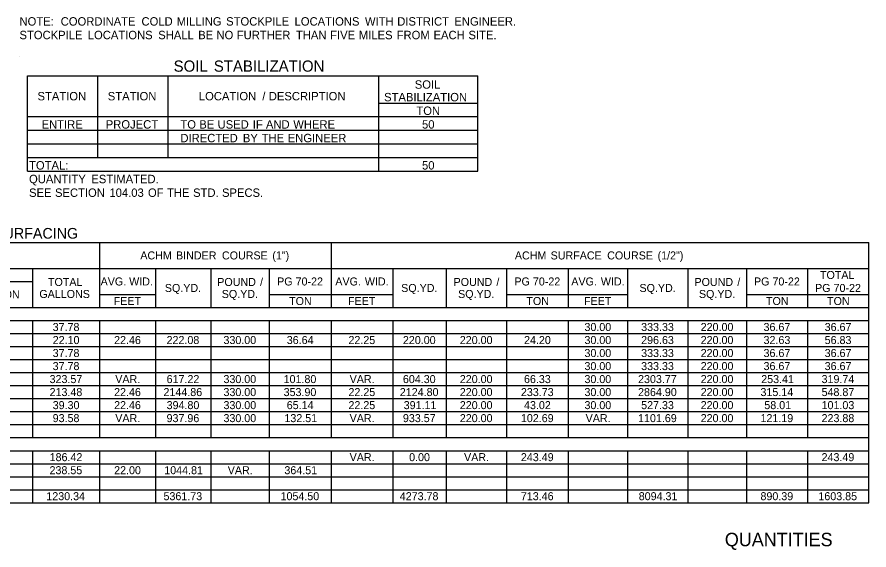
# Model space of a CAD drawing. Extents: x 1334738 to 1334853, y 402732 to 402753.
# Drawn here: x 1334837.83 to 1334853.05, y 402732.57 to 402742.09 of the extents above; entities that cross this region are included whole.
import ezdxf

# ---------------------------------------------------------------- set-up
doc = ezdxf.new("R2010")
doc.units = 0
doc.layers.add('Default', color=7, linetype='Continuous')
doc.layers.add('R_No Plot', color=7, linetype='Continuous')

msp = doc.modelspace()

# ---------------------------------------------------------------- linework, layer by layer
at = {"layer": 'Default'}
for p, q in [((1334837.87, 402741.381), (1334837.87, 402741.381)), ((1334838.016, 402741.04), (1334846.06, 402741.04)), ((1334838.016, 402739.334), (1334838.016, 402741.04)), ((1334838.016, 402739.334), (1334838.016, 402741.04)), ((1334839.272, 402739.577), (1334839.272, 402741.04)), ((1334840.527, 402739.577), (1334840.527, 402741.04)), ((1334844.293, 402739.334), (1334844.293, 402741.04)), ((1334846.06, 402739.334), (1334846.06, 402741.04)), ((1334846.06, 402739.334), (1334846.06, 402741.04)), ((1334844.293, 402740.552), (1334846.06, 402740.552)), ((1334838.016, 402740.309), (1334846.06, 402740.309)), ((1334838.016, 402740.309), (1334846.06, 402740.309)), ((1334839.272, 402739.577), (1334839.272, 402740.309)), ((1334840.527, 402739.577), (1334840.527, 402740.309)), ((1334844.293, 402739.577), (1334844.293, 402740.309)), ((1334838.016, 402740.065), (1334846.06, 402740.065)), ((1334838.016, 402739.821), (1334846.06, 402739.821)), ((1334838.016, 402739.577), (1334839.272, 402739.577)), ((1334838.016, 402739.577), (1334846.06, 402739.577)), ((1334838.016, 402739.334), (1334846.06, 402739.334)), ((1334821.913, 402738.063), (1334853.053, 402738.063)), ((1334839.307, 402736.901), (1334839.307, 402738.063)), ((1334843.444, 402737.598), (1334843.444, 402738.063)), ((1334843.444, 402736.901), (1334843.444, 402738.063)), ((1334853.053, 402733.647), (1334853.053, 402738.063)), ((1334853.053, 402733.415), (1334853.053, 402738.063)), ((1334828.745, 402737.598), (1334853.053, 402737.598)), ((1334838.11, 402736.901), (1334838.11, 402737.598)), ((1334838.11, 402736.901), (1334838.11, 402737.598)), ((1334840.306, 402736.901), (1334840.306, 402737.598)), ((1334841.294, 402736.901), (1334841.294, 402737.598)), ((1334842.34, 402736.901), (1334842.34, 402737.598)), ((1334844.547, 402737.598), (1334845.5, 402737.598)), ((1334844.547, 402736.901), (1334844.547, 402737.598)), ((1334845.5, 402736.901), (1334845.5, 402737.598)), ((1334846.581, 402736.901), (1334846.581, 402737.598)), ((1334847.685, 402736.901), (1334847.685, 402737.598)), ((1334848.742, 402737.598), (1334849.823, 402737.598)), ((1334848.742, 402736.901), (1334848.742, 402737.598)), ((1334849.823, 402736.901), (1334849.823, 402737.598)), ((1334850.868, 402736.901), (1334850.868, 402737.598)), ((1334851.961, 402736.901), (1334851.961, 402737.598)), ((1334830.929, 402737.366), (1334838.11, 402737.366)), ((1334839.307, 402737.133), (1334840.306, 402737.133)), ((1334840.306, 402736.901), (1334840.306, 402737.133)), ((1334842.34, 402737.133), (1334844.547, 402737.133)), ((1334843.444, 402736.901), (1334843.444, 402737.133)), ((1334844.547, 402736.901), (1334844.547, 402737.133)), ((1334846.581, 402737.133), (1334848.742, 402737.133)), ((1334847.685, 402736.901), (1334847.685, 402737.133)), ((1334848.742, 402736.901), (1334848.742, 402737.133)), ((1334850.868, 402737.133), (1334853.053, 402737.133)), ((1334821.913, 402736.901), (1334853.053, 402736.901)), ((1334836.913, 402736.901), (1334840.306, 402736.901)), ((1334840.306, 402736.901), (1334844.547, 402736.901)), ((1334844.547, 402736.901), (1334848.742, 402736.901)), ((1334848.742, 402736.901), (1334853.053, 402736.901)), ((1334821.913, 402736.668), (1334853.053, 402736.668)), ((1334838.11, 402734.577), (1334838.11, 402736.668)), ((1334838.11, 402734.577), (1334838.11, 402736.668)), ((1334839.307, 402734.577), (1334839.307, 402736.668)), ((1334839.307, 402734.577), (1334839.307, 402736.668)), ((1334840.306, 402734.577), (1334840.306, 402736.668)), ((1334840.306, 402734.577), (1334840.306, 402736.668)), ((1334841.294, 402734.577), (1334841.294, 402736.668)), ((1334841.294, 402734.577), (1334841.294, 402736.668)), ((1334842.34, 402734.577), (1334842.34, 402736.668)), ((1334842.34, 402734.577), (1334842.34, 402736.668)), ((1334843.444, 402734.577), (1334843.444, 402736.668)), ((1334843.444, 402734.577), (1334843.444, 402736.668)), ((1334844.547, 402734.577), (1334844.547, 402736.668)), ((1334844.547, 402734.577), (1334844.547, 402736.668)), ((1334845.5, 402734.577), (1334845.5, 402736.668)), ((1334845.5, 402734.577), (1334845.5, 402736.668)), ((1334846.581, 402734.577), (1334846.581, 402736.668)), ((1334846.581, 402734.577), (1334846.581, 402736.668)), ((1334847.685, 402734.577), (1334847.685, 402736.668)), ((1334847.685, 402734.577), (1334847.685, 402736.668)), ((1334848.742, 402734.577), (1334848.742, 402736.668)), ((1334848.742, 402734.577), (1334848.742, 402736.668)), ((1334849.823, 402734.577), (1334849.823, 402736.668)), ((1334849.823, 402734.577), (1334849.823, 402736.668)), ((1334850.868, 402734.577), (1334850.868, 402736.668)), ((1334850.868, 402734.577), (1334850.868, 402736.668)), ((1334851.961, 402734.577), (1334851.961, 402736.668)), ((1334851.961, 402734.577), (1334851.961, 402736.668)), ((1334821.913, 402736.436), (1334853.053, 402736.436)), ((1334821.913, 402736.204), (1334853.053, 402736.204)), ((1334821.913, 402735.971), (1334853.053, 402735.971)), ((1334821.913, 402735.739), (1334853.053, 402735.739)), ((1334821.913, 402735.506), (1334853.053, 402735.506)), ((1334821.913, 402735.274), (1334853.053, 402735.274)), ((1334821.913, 402735.042), (1334853.053, 402735.042)), ((1334821.913, 402734.809), (1334853.053, 402734.809)), ((1334821.913, 402734.577), (1334853.053, 402734.577)), ((1334835.717, 402734.577), (1334839.307, 402734.577)), ((1334839.307, 402734.577), (1334848.742, 402734.577)), ((1334848.742, 402734.577), (1334849.823, 402734.577)), ((1334849.823, 402734.577), (1334851.961, 402734.577)), ((1334851.961, 402734.577), (1334853.053, 402734.577)), ((1334821.913, 402734.344), (1334853.053, 402734.344)), ((1334838.11, 402733.647), (1334838.11, 402734.344)), ((1334838.11, 402733.415), (1334838.11, 402734.344)), ((1334839.307, 402733.647), (1334839.307, 402734.344)), ((1334839.307, 402733.415), (1334839.307, 402734.344)), ((1334840.306, 402733.415), (1334840.306, 402734.344)), ((1334840.306, 402733.415), (1334840.306, 402734.344)), ((1334841.294, 402733.415), (1334841.294, 402734.344)), ((1334841.294, 402733.415), (1334841.294, 402734.344)), ((1334842.34, 402733.415), (1334842.34, 402734.344)), ((1334842.34, 402733.415), (1334842.34, 402734.344)), ((1334843.444, 402733.415), (1334843.444, 402734.344)), ((1334843.444, 402733.415), (1334843.444, 402734.344)), ((1334844.547, 402733.415), (1334844.547, 402734.344)), ((1334844.547, 402733.415), (1334844.547, 402734.344)), ((1334845.5, 402733.415), (1334845.5, 402734.344)), ((1334845.5, 402733.415), (1334845.5, 402734.344)), ((1334846.581, 402733.415), (1334846.581, 402734.344)), ((1334846.581, 402733.415), (1334846.581, 402734.344)), ((1334847.685, 402733.415), (1334847.685, 402734.344)), ((1334847.685, 402733.415), (1334847.685, 402734.344)), ((1334848.742, 402733.415), (1334848.742, 402734.344)), ((1334848.742, 402733.415), (1334848.742, 402734.344)), ((1334849.823, 402733.415), (1334849.823, 402734.344)), ((1334849.823, 402733.415), (1334849.823, 402734.344)), ((1334850.868, 402733.415), (1334850.868, 402734.344)), ((1334850.868, 402733.415), (1334850.868, 402734.344)), ((1334851.961, 402733.415), (1334851.961, 402734.344)), ((1334851.961, 402733.415), (1334851.961, 402734.344)), ((1334821.913, 402734.112), (1334853.053, 402734.112)), ((1334821.913, 402733.88), (1334853.053, 402733.88)), ((1334821.913, 402733.647), (1334853.053, 402733.647)), ((1334821.913, 402733.647), (1334853.053, 402733.647)), ((1334821.913, 402733.415), (1334853.053, 402733.415))]:
    msp.add_line(p, q, dxfattribs=at)

# ---------------------------------------------------------------- texts
for s, height, p in [('NOTE:', 0.15, (1334837.87, 402741.934)), (' COORDINATE', 0.15, (1334838.551, 402741.934)), (' COLD', 0.15, (1334839.995, 402741.934)), (' MILLING', 0.15, (1334840.624, 402741.934)), (' STOCKPILE', 0.15, (1334841.508, 402741.934)), (' LOCATIONS', 0.15, (1334842.731, 402741.934)), (' WITH', 0.15, (1334843.989, 402741.934)), (' DISTRICT', 0.15, (1334844.566, 402741.934)), (' ENGINEER.', 0.15, (1334845.587, 402741.934)), ('STOCKPILE', 0.15, (1334837.87, 402741.691)), (' LOCATIONS', 0.15, (1334839.035, 402741.691)), (' SHALL', 0.15, (1334840.294, 402741.691)), (' BE', 0.15, (1334841.009, 402741.691)), (' NO', 0.15, (1334841.335, 402741.691)), (' FURTHER', 0.15, (1334841.698, 402741.691)), (' THAN', 0.15, (1334842.755, 402741.691)), (' FIVE', 0.15, (1334843.367, 402741.691)), (' MILES', 0.15, (1334843.88, 402741.691)), (' FROM', 0.15, (1334844.556, 402741.691)), (' EACH', 0.15, (1334845.215, 402741.691)), (' SITE.', 0.15, (1334845.839, 402741.691)), ('SOIL', 0.2, (1334840.625, 402741.111)), (' STABILIZATION', 0.2, (1334841.269, 402741.111)), ('SOIL', 0.15, (1334844.935, 402740.807)), ('STATION', 0.15, (1334838.192, 402740.599)), ('STATION', 0.15, (1334839.448, 402740.599)), ('LOCATION', 0.15, (1334841.076, 402740.599)), (' /', 0.15, (1334842.154, 402740.599)), (' DESCRIPTION', 0.15, (1334842.27, 402740.599)), ('STABILIZATION', 0.15, (1334844.387, 402740.582)), ('TON', 0.15, (1334844.964, 402740.339)), ('ENTIRE', 0.15, (1334838.265, 402740.095)), ('PROJECT', 0.15, (1334839.412, 402740.095)), ('TO', 0.15, (1334840.746, 402740.095)), (' BE', 0.15, (1334841.028, 402740.095)), (' USED', 0.15, (1334841.355, 402740.095)), (' IF', 0.15, (1334841.984, 402740.095)), (' AND', 0.15, (1334842.219, 402740.095)), (' WHERE', 0.15, (1334842.708, 402740.095)), ('50', 0.15, (1334845.065, 402740.095)), ('DIRECTED', 0.15, (1334840.746, 402739.851)), (' BY', 0.15, (1334841.807, 402739.851)), (' THE', 0.15, (1334842.143, 402739.851)), (' ENGINEER', 0.15, (1334842.609, 402739.851)), ('TOTAL:', 0.15, (1334838.041, 402739.364)), ('50', 0.15, (1334845.065, 402739.364)), ('QUANTITY', 0.15, (1334838.041, 402739.12)), (' ESTIMATED.', 0.15, (1334839.099, 402739.12)), ('SEE', 0.15, (1334838.041, 402738.876)), (' SECTION', 0.15, (1334838.449, 402738.876)), (' 104.03', 0.15, (1334839.422, 402738.876)), (' OF', 0.15, (1334840.111, 402738.876)), (' THE', 0.15, (1334840.451, 402738.876)), (' STD.', 0.15, (1334840.917, 402738.876)), (' SPECS.', 0.15, (1334841.434, 402738.876)), (' SURFACING', 0.1907, (1334837.345, 402738.13)), ('ACHM', 0.143, (1334840.03, 402737.759)), (' BINDER', 0.143, (1334840.615, 402737.759)), (' COURSE', 0.143, (1334841.436, 402737.759)), (' (1")', 0.143, (1334842.336, 402737.759)), ('ACHM', 0.143, (1334846.724, 402737.759)), (' SURFACE', 0.143, (1334847.31, 402737.759)), (' COURSE', 0.143, (1334848.321, 402737.759)), (' (1/2")', 0.143, (1334849.222, 402737.759)), ('AVG. WID.', 0.143, (1334839.32, 402737.294)), (' /', 0.143, (1334842.117, 402737.285)), ('PG', 0.143, (1334842.475, 402737.294)), (' 70-22', 0.143, (1334842.752, 402737.294)), ('AVG.', 0.143, (1334843.515, 402737.294)), (' WID.', 0.143, (1334843.99, 402737.294)), (' /', 0.143, (1334846.341, 402737.285)), ('PG', 0.143, (1334846.716, 402737.294)), (' 70-22', 0.143, (1334846.993, 402737.294)), ('AVG.', 0.143, (1334847.733, 402737.294)), (' WID.', 0.143, (1334848.208, 402737.294)), (' /', 0.143, (1334850.646, 402737.285)), ('PG', 0.143, (1334850.998, 402737.294)), (' 70-22', 0.143, (1334851.275, 402737.294)), ('TOTAL', 0.143, (1334852.177, 402737.41)), ('TOTAL', 0.143, (1334838.379, 402737.285)), ('SQ.YD.', 0.143, (1334840.468, 402737.178)), ('POUND', 0.143, (1334841.405, 402737.285)), ('SQ.YD.', 0.143, (1334844.692, 402737.178)), ('POUND', 0.143, (1334845.629, 402737.285)), ('SQ.YD.', 0.143, (1334848.951, 402737.178)), ('POUND', 0.143, (1334849.934, 402737.285)), ('PG', 0.143, (1334852.09, 402737.178)), (' 70-22', 0.143, (1334852.367, 402737.178)), ('GALLON', 0.143, (1334837.098, 402737.062)), ('GALLONS', 0.143, (1334838.225, 402737.071)), ('SQ.YD.', 0.143, (1334841.485, 402737.071)), ('SQ.YD.', 0.143, (1334845.709, 402737.071)), ('SQ.YD.', 0.143, (1334850.014, 402737.071)), ('FEET', 0.143, (1334839.553, 402736.945)), ('TON', 0.143, (1334842.689, 402736.945)), ('FEET', 0.143, (1334843.742, 402736.945)), ('TON', 0.143, (1334846.93, 402736.945)), ('FEET', 0.143, (1334847.96, 402736.945)), ('TON', 0.143, (1334851.212, 402736.945)), ('TON', 0.143, (1334852.304, 402736.945)), ('37.78', 0.143, (1334838.463, 402736.481)), ('30.00', 0.143, (1334847.968, 402736.481)), ('333.33', 0.143, (1334848.981, 402736.481)), ('220.00', 0.143, (1334850.045, 402736.481)), ('36.67', 0.143, (1334851.169, 402736.481)), ('36.67', 0.143, (1334852.261, 402736.481)), ('22.10', 0.143, (1334838.464, 402736.248)), ('22.46', 0.143, (1334839.561, 402736.248)), ('222.08', 0.143, (1334840.499, 402736.248)), ('330.00', 0.143, (1334841.516, 402736.248)), ('36.64', 0.143, (1334842.647, 402736.248)), ('22.25', 0.143, (1334843.75, 402736.248)), ('220.00', 0.143, (1334844.723, 402736.248)), ('220.00', 0.143, (1334845.74, 402736.248)), ('24.20', 0.143, (1334846.888, 402736.248)), ('30.00', 0.143, (1334847.968, 402736.248)), ('296.63', 0.143, (1334848.981, 402736.248)), ('220.00', 0.143, (1334850.045, 402736.248)), ('32.63', 0.143, (1334851.169, 402736.248)), ('56.83', 0.143, (1334852.261, 402736.248)), ('37.78', 0.143, (1334838.463, 402736.016)), ('30.00', 0.143, (1334847.968, 402736.016)), ('333.33', 0.143, (1334848.981, 402736.016)), ('220.00', 0.143, (1334850.045, 402736.016)), ('36.67', 0.143, (1334851.169, 402736.016)), ('36.67', 0.143, (1334852.261, 402736.016)), ('37.78', 0.143, (1334838.463, 402735.783)), ('30.00', 0.143, (1334847.968, 402735.783)), ('333.33', 0.143, (1334848.981, 402735.783)), ('220.00', 0.143, (1334850.045, 402735.783)), ('36.67', 0.143, (1334851.169, 402735.783)), ('36.67', 0.143, (1334852.261, 402735.783)), ('323.57', 0.143, (1334838.408, 402735.551)), ('VAR.', 0.143, (1334839.582, 402735.551)), ('617.22', 0.143, (1334840.5, 402735.551)), ('330.00', 0.143, (1334841.516, 402735.551)), ('101.80', 0.143, (1334842.591, 402735.551)), ('VAR.', 0.143, (1334843.771, 402735.551)), ('604.30', 0.143, (1334844.723, 402735.551)), ('220.00', 0.143, (1334845.74, 402735.551)), ('66.33', 0.143, (1334846.887, 402735.551)), ('30.00', 0.143, (1334847.968, 402735.551)), ('2303.77', 0.143, (1334848.926, 402735.551)), ('220.00', 0.143, (1334850.045, 402735.551)), ('253.41', 0.143, (1334851.127, 402735.551)), ('319.74', 0.143, (1334852.206, 402735.551)), ('213.48', 0.143, (1334838.408, 402735.319)), ('22.46', 0.143, (1334839.561, 402735.319)), ('2144.86', 0.143, (1334840.444, 402735.319)), ('330.00', 0.143, (1334841.516, 402735.319)), ('353.90', 0.143, (1334842.591, 402735.319)), ('22.25', 0.143, (1334843.75, 402735.319)), ('2124.80', 0.143, (1334844.668, 402735.319)), ('220.00', 0.143, (1334845.74, 402735.319)), ('233.73', 0.143, (1334846.832, 402735.319)), ('30.00', 0.143, (1334847.968, 402735.319)), ('2864.90', 0.143, (1334848.926, 402735.319)), ('220.00', 0.143, (1334850.045, 402735.319)), ('315.14', 0.143, (1334851.114, 402735.319)), ('548.87', 0.143, (1334852.206, 402735.319)), ('39.30', 0.143, (1334838.464, 402735.086)), ('22.46', 0.143, (1334839.561, 402735.086)), ('394.80', 0.143, (1334840.5, 402735.086)), ('330.00', 0.143, (1334841.516, 402735.086)), ('65.14', 0.143, (1334842.647, 402735.086)), ('22.25', 0.143, (1334843.75, 402735.086)), ('391.11', 0.143, (1334844.737, 402735.086)), ('220.00', 0.143, (1334845.74, 402735.086)), ('43.02', 0.143, (1334846.888, 402735.086)), ('30.00', 0.143, (1334847.968, 402735.086)), ('527.33', 0.143, (1334848.981, 402735.086)), ('220.00', 0.143, (1334850.045, 402735.086)), ('58.01', 0.143, (1334851.183, 402735.086)), ('101.03', 0.143, (1334852.206, 402735.086)), ('93.58', 0.143, (1334838.463, 402734.854)), ('937.96', 0.143, (1334840.499, 402734.854)), ('330.00', 0.143, (1334841.516, 402734.854)), ('132.51', 0.143, (1334842.605, 402734.854)), ('933.57', 0.143, (1334844.723, 402734.854)), ('220.00', 0.143, (1334845.74, 402734.854)), ('102.69', 0.143, (1334846.832, 402734.854)), ('1101.69', 0.143, (1334848.926, 402734.854)), ('220.00', 0.143, (1334850.045, 402734.854)), ('121.19', 0.143, (1334851.114, 402734.854)), ('223.88', 0.143, (1334852.206, 402734.854)), ('VAR.', 0.143, (1334839.582, 402734.854)), ('VAR.', 0.143, (1334843.771, 402734.854)), ('VAR.', 0.143, (1334847.989, 402734.854)), ('186.42', 0.143, (1334838.409, 402734.157)), ('VAR.', 0.143, (1334843.771, 402734.157)), ('0.00', 0.143, (1334844.834, 402734.157)), ('VAR.', 0.143, (1334845.816, 402734.157)), ('243.49', 0.143, (1334846.832, 402734.157)), ('243.49', 0.143, (1334852.206, 402734.157)), ('238.55', 0.143, (1334838.407, 402733.924)), ('22.00', 0.143, (1334839.562, 402733.924)), ('1044.81', 0.143, (1334840.458, 402733.924)), ('VAR.', 0.143, (1334841.592, 402733.924)), ('364.51', 0.143, (1334842.605, 402733.924)), ('1230.34', 0.143, (1334838.35, 402733.46)), ('5361.73', 0.143, (1334840.444, 402733.46)), ('1054.50', 0.143, (1334842.536, 402733.46)), ('4273.78', 0.143, (1334844.667, 402733.46)), ('713.46', 0.143, (1334846.831, 402733.46)), ('8094.31', 0.143, (1334848.938, 402733.46)), ('890.39', 0.143, (1334851.114, 402733.46)), ('1603.85', 0.143, (1334852.149, 402733.46))]:
    msp.add_text(s, height=height, dxfattribs=at).set_placement(p)
at = {"layer": 'R_No Plot'}
msp.add_text('QUANTITIES', height=0.24, dxfattribs=at).set_placement((1334850.477, 402732.638))

doc.saveas('drawing.dxf')
